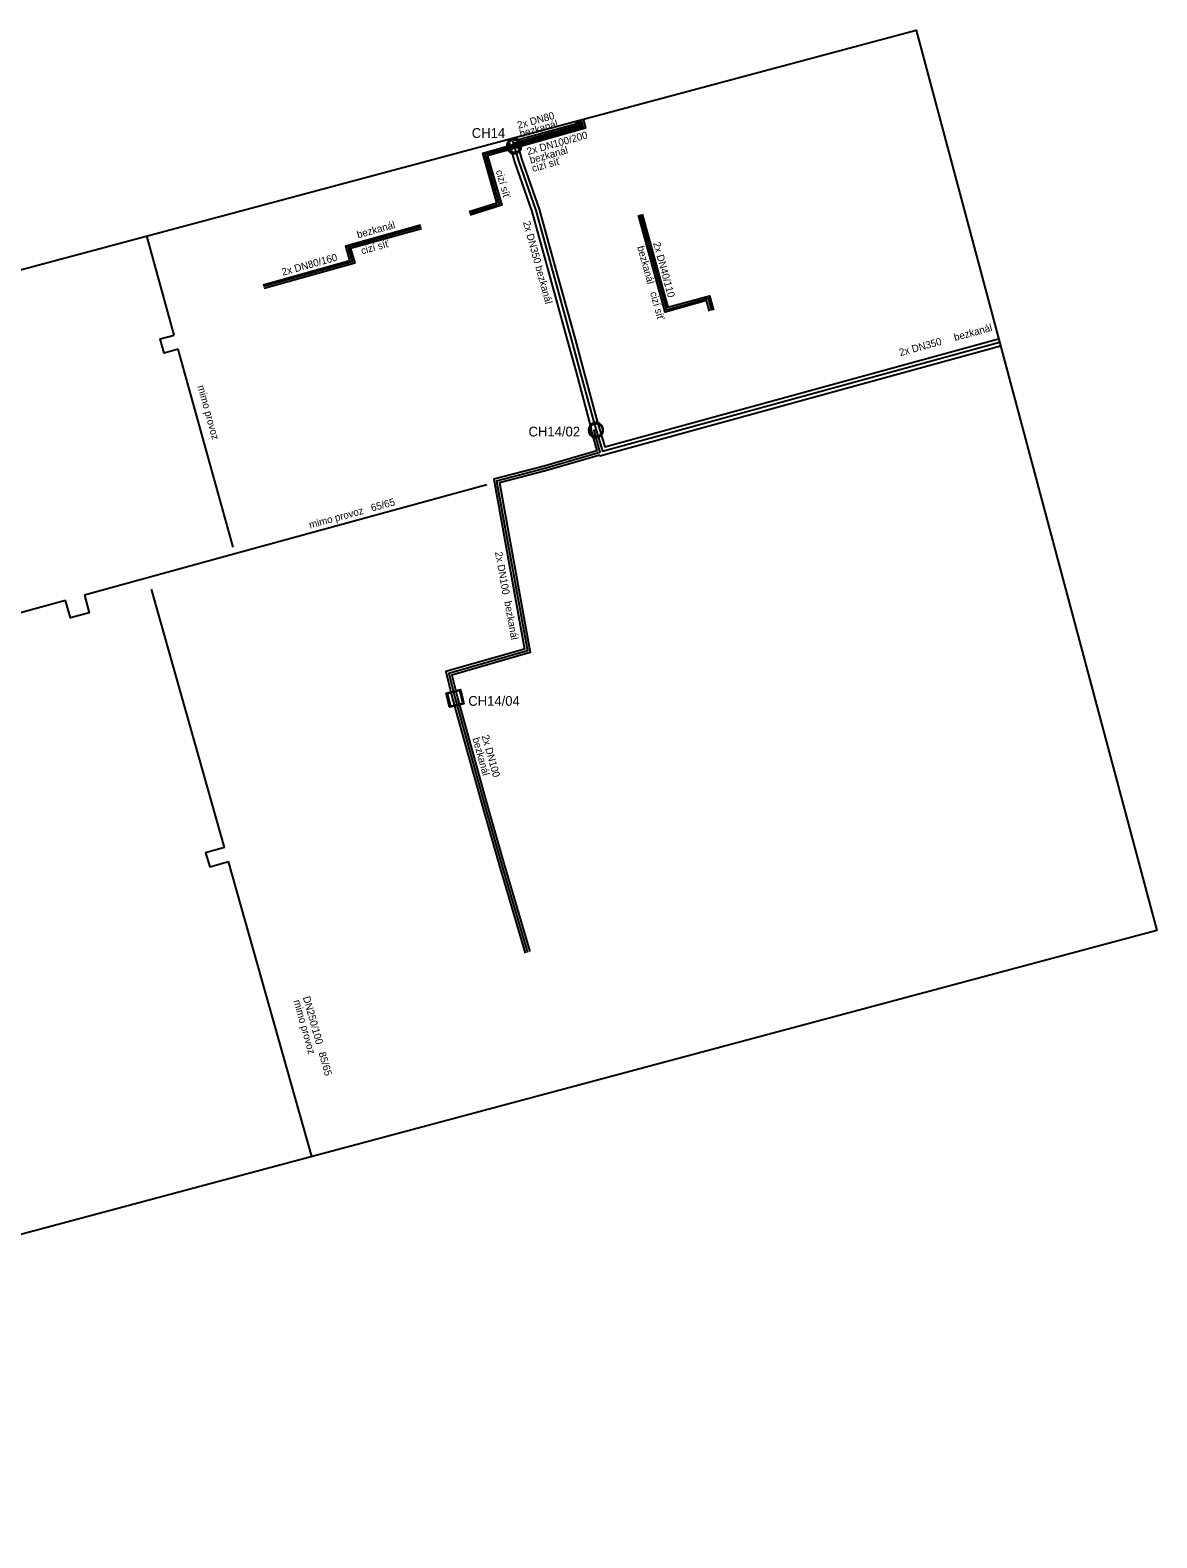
# Model space of a CAD drawing. Extents: x -599341 to -598827, y -1159084 to -1158776.
# Drawn here: x -599057.8 to -598827, y -1159084.3 to -1158775.6 of the extents above; entities that cross this region are included whole.
import ezdxf

# ---------------------------------------------------------------- set-up
doc = ezdxf.new("R2010")
doc.units = 0
for name, color, linetype in [('Horkovod - trasa - okraj', 7, 'Continuous'), ('Horkovod - trasa popis', 7, 'Continuous'), ('Horkovod - trasa popis 2', 7, 'Continuous'), ('Horkovod - trasa popis 3', 7, 'Continuous'), ('Level 46', 7, 'Continuous'), ('Osa trasy horkovodu', 7, 'Continuous'), ('Osa trasy parovodu', 7, 'Continuous'), ('označení', 7, 'Continuous'), ('Parovod - trasa popis', 7, 'Continuous'), ('Parovod - trasa popis 2', 7, 'Continuous'), ('Uzel trasy horkovodu', 7, 'Continuous'), ('Šachta trasy horkovodu', 7, 'Continuous')]:
    doc.layers.add(name, color=color, linetype=linetype)

msp = doc.modelspace()

# ---------------------------------------------------------------- linework, layer by layer
at = {"layer": 'Horkovod - trasa - okraj'}
msp.add_line((-598958.36, -1158797.54), (-598958.2, -1158798.12), dxfattribs=at)
for points in [[(-598967.87, -1158812.7), (-598962.15, -1158810.93), (-598965.07, -1158800.75), (-598945, -1158795.08), (-598945.28, -1158794.04)], [(-598944.51, -1158793.84), (-598944.03, -1158795.64), (-598964.08, -1158801.3), (-598961.17, -1158811.46), (-598967.63, -1158813.46)], [(-598945.18, -1158794.02), (-598944.86, -1158795.24), (-598958.71, -1158799.09)], [(-598958.2, -1158798.12), (-598945.83, -1158794.68), (-598945.95, -1158794.22)], [(-598959.36, -1158799.55), (-598959.54, -1158798.91), (-598959.81, -1158797.93)], [(-598957.81, -1158799.53), (-598957.06, -1158802.12), (-598953.49, -1158812.27), (-598950.63, -1158822.67), (-598946.16, -1158838.89), (-598944.44, -1158845.25), (-598941.49, -1158856.17)], [(-598942.76, -1158857.21), (-598945.89, -1158845.64), (-598947.61, -1158839.29), (-598952.08, -1158823.07), (-598954.92, -1158812.72), (-598958.49, -1158802.57), (-598959.25, -1158799.93)], [(-598918.61, -1158833.13), (-598919.21, -1158830.97), (-598927.71, -1158833.32), (-598933.19, -1158813.48)], [(-598932.42, -1158813.26), (-598927.16, -1158832.34), (-598918.65, -1158829.99), (-598917.84, -1158832.92)], [(-599010.05, -1158827.72), (-598992.28, -1158822.75), (-598993.12, -1158819.76), (-598977.8, -1158815.48)], [(-598977.59, -1158816.25), (-598992.13, -1158820.32), (-598991.29, -1158823.3), (-599009.84, -1158828.49)], [(-598941.49, -1158856.15), (-598940.06, -1158860.91), (-598859.42, -1158838.77)], [(-598941.11, -1158862.63), (-598941.08, -1158862.75), (-598859.03, -1158840.22)], [(-598942.76, -1158857.21), (-598942.93, -1158857.27), (-598941.67, -1158861.75), (-598952.49, -1158864.85), (-598962.8, -1158867.55), (-598956.48, -1158902.33), (-598972.63, -1158906.94), (-598971.23, -1158912.54)], [(-598941.11, -1158862.63), (-598952.23, -1158865.82), (-598961.65, -1158868.29), (-598955.33, -1158903.04), (-598971.42, -1158907.64), (-598970.26, -1158912.29)], [(-598971.23, -1158912.54), (-598964.96, -1158935.04), (-598961.72, -1158946.52), (-598956.35, -1158964.56)], [(-598970.26, -1158912.29), (-598964, -1158934.78), (-598960.76, -1158946.24), (-598955.4, -1158964.27)]]:
    msp.add_lwpolyline(points, dxfattribs=at)
at = {"layer": 'Level 46'}
msp.add_lwpolyline([(-599341.24, -1158899.96), (-598876.32, -1158775.6), (-598827.01, -1158959.94), (-599291.93, -1159084.3)], close=True, dxfattribs=at)
msp.add_lwpolyline([(-599341.24, -1158899.96), (-598876.32, -1158775.6), (-598827.01, -1158959.94), (-599291.93, -1159084.3)], close=True, dxfattribs=at)
at = {"layer": 'Osa trasy horkovodu'}
for points in [[(-598967.75, -1158813.08), (-598961.66, -1158811.2), (-598964.57, -1158801.02), (-598944.52, -1158795.36), (-598944.89, -1158793.94)], [(-598958.82, -1158798.71), (-598945.35, -1158794.96), (-598945.57, -1158794.12)], [(-598959.08, -1158797.73), (-598958.82, -1158798.71), (-598958.64, -1158799.35)], [(-598958.64, -1158799.35), (-598957.77, -1158802.34), (-598954.2, -1158812.49), (-598951.35, -1158822.87), (-598946.88, -1158839.09), (-598945.16, -1158845.45), (-598942.21, -1158856.36)], [(-598932.81, -1158813.37), (-598927.44, -1158832.83), (-598918.93, -1158830.48), (-598918.23, -1158833.03)], [(-598977.7, -1158815.86), (-598992.62, -1158820.04), (-598991.79, -1158823.02), (-599009.95, -1158828.1)], [(-598942.21, -1158856.36), (-598940.57, -1158861.83), (-598859.23, -1158839.5)], [(-598941.89, -1158857.48), (-598942.31, -1158857.6), (-598941.06, -1158862.09), (-598952.36, -1158865.33), (-598962.22, -1158867.92), (-598955.91, -1158902.69), (-598972.03, -1158907.29), (-598970.74, -1158912.42)], [(-598970.74, -1158912.42), (-598964.48, -1158934.91), (-598961.24, -1158946.38), (-598955.88, -1158964.42)]]:
    msp.add_lwpolyline(points, dxfattribs=at)
at = {"layer": 'Osa trasy parovodu'}
for p, q in [((-599028.25, -1158838.02), (-599033.88, -1158817.74)), ((-599016.19, -1158881.44), (-599027.45, -1158840.91)), ((-598964.21, -1158868.66), (-599015.81, -1158882.84)), ((-599015.81, -1158882.84), (-599046.63, -1158891.31)), ((-599017.96, -1158942.93), (-599032.91, -1158890.08)), ((-599050.49, -1158892.36), (-599074.08, -1158898.85)), ((-599000.05, -1159006.22), (-599017.14, -1158945.81))]:
    msp.add_line(p, q, dxfattribs=at)
for points in [[(-599027.45, -1158840.91), (-599030.33, -1158841.71), (-599031.14, -1158838.82), (-599028.25, -1158838.02)], [(-599046.63, -1158891.31), (-599045.66, -1158894.87), (-599049.51, -1158895.93), (-599050.49, -1158892.36)], [(-599017.96, -1158942.93), (-599021.81, -1158944.02), (-599020.99, -1158946.9), (-599017.14, -1158945.81)]]:
    msp.add_lwpolyline(points, dxfattribs=at)
at = {"layer": 'Uzel trasy horkovodu'}
for points in [[(-598957.19, -1158798.93), (-598957.09, -1158799.29), (-598957.17, -1158799.69), (-598957.26, -1158800.09), (-598957.55, -1158800.38), (-598957.84, -1158800.68), (-598958.22, -1158800.79), (-598958.59, -1158800.9), (-598958.99, -1158800.81), (-598959.39, -1158800.72), (-598959.68, -1158800.43), (-598959.97, -1158800.14), (-598960.08, -1158799.76), (-598960.19, -1158799.39), (-598960.1, -1158798.99), (-598960.01, -1158798.59), (-598959.72, -1158798.3), (-598959.43, -1158798.01), (-598959.06, -1158797.9), (-598958.68, -1158797.79), (-598958.28, -1158797.89), (-598957.87, -1158797.98), (-598957.59, -1158798.27), (-598957.3, -1158798.56), (-598957.19, -1158798.93)], [(-598957.37, -1158798.98), (-598957.47, -1158798.66), (-598957.72, -1158798.4), (-598957.97, -1158798.15), (-598958.32, -1158798.07), (-598958.67, -1158797.99), (-598959, -1158798.08), (-598959.33, -1158798.18), (-598959.58, -1158798.43), (-598959.84, -1158798.69), (-598959.92, -1158799.03), (-598960, -1158799.38), (-598959.9, -1158799.71), (-598959.8, -1158800.04), (-598959.55, -1158800.29), (-598959.3, -1158800.55), (-598958.95, -1158800.63), (-598958.6, -1158800.7), (-598958.27, -1158800.61), (-598957.94, -1158800.51), (-598957.69, -1158800.25), (-598957.43, -1158799.99), (-598957.36, -1158799.65), (-598957.28, -1158799.3), (-598957.37, -1158798.98)], [(-598940.44, -1158857.04), (-598940.34, -1158857.4), (-598940.42, -1158857.8), (-598940.5, -1158858.2), (-598940.79, -1158858.5), (-598941.08, -1158858.8), (-598941.45, -1158858.91), (-598941.83, -1158859.03), (-598942.23, -1158858.94), (-598942.62, -1158858.85), (-598942.92, -1158858.57), (-598943.21, -1158858.28), (-598943.32, -1158857.9), (-598943.43, -1158857.53), (-598943.35, -1158857.13), (-598943.26, -1158856.73), (-598942.98, -1158856.44), (-598942.69, -1158856.15), (-598942.32, -1158856.04), (-598941.94, -1158855.92), (-598941.54, -1158856.01), (-598941.13, -1158856.1), (-598940.84, -1158856.39), (-598940.55, -1158856.68), (-598940.44, -1158857.04)], [(-598940.62, -1158857.09), (-598940.72, -1158856.78), (-598940.97, -1158856.52), (-598941.23, -1158856.27), (-598941.58, -1158856.19), (-598941.93, -1158856.12), (-598942.26, -1158856.22), (-598942.59, -1158856.31), (-598942.84, -1158856.57), (-598943.09, -1158856.82), (-598943.16, -1158857.17), (-598943.24, -1158857.52), (-598943.14, -1158857.85), (-598943.04, -1158858.18), (-598942.79, -1158858.43), (-598942.53, -1158858.68), (-598942.18, -1158858.76), (-598941.83, -1158858.83), (-598941.51, -1158858.73), (-598941.18, -1158858.63), (-598940.92, -1158858.37), (-598940.67, -1158858.11), (-598940.6, -1158857.76), (-598940.53, -1158857.41), (-598940.62, -1158857.09)]]:
    msp.add_open_spline(points, degree=3, dxfattribs=at)
at = {"layer": 'Šachta trasy horkovodu'}
for points in [[(-598972.56, -1158911.32), (-598969.65, -1158910.59), (-598968.92, -1158913.51), (-598971.84, -1158914.24), (-598972.56, -1158911.32)], [(-598971.7, -1158914.01), (-598969.15, -1158913.37), (-598969.78, -1158910.82), (-598972.34, -1158911.46), (-598971.7, -1158914.01)]]:
    msp.add_lwpolyline(points, dxfattribs=at)

# ---------------------------------------------------------------- texts
at = {"layer": 'Horkovod - trasa popis'}
for s, rotation, p in [('2x DN80', 15.5511, (-598957.76, -1158795.81)), ('2x DN100/200', 15.7622, (-598955.8, -1158801.19)), ('2x DN350 bezkanál', 285.3606, (-598956.84, -1158814.91)), ('2x DN40/110', 285.4273, (-598930.2, -1158819.19)), ('2x DN80/160', 15.628, (-599006, -1158825.89)), ('2x DN100', 280.3037, (-598962.57, -1158882.51)), ('2x DN100', 285.5575, (-598965.3, -1158920.11))]:
    msp.add_text(s, height=1.5, rotation=rotation, dxfattribs=at).set_placement(p)
at = {"layer": 'Horkovod - trasa popis 2'}
for s, rotation, p in [('bezkanál', 15.5511, (-598957.29, -1158797.56)), ('bezkanál', 15.7622, (-598955.22, -1158802.96)), ('bezkanál', 15.6281, (-598990.61, -1158818.24)), ('bezkanál', 285.4273, (-598933.45, -1158819.98)), ('2x DN350', 15.3516, (-598879.56, -1158842.35)), ('bezkanál', 280.3037, (-598960.66, -1158892.62)), ('bezkanál', 285.5575, (-598967.18, -1158920.63))]:
    msp.add_text(s, height=1.5, rotation=rotation, dxfattribs=at).set_placement(p)
at = {"layer": 'Horkovod - trasa popis 3'}
for s, rotation, p in [('cizí síť', 15.7622, (-598954.77, -1158804.65)), ('cizí síť', 285.9805, (-598962.42, -1158804.44)), ('cizí síť', 15.6281, (-598989.79, -1158821.53)), ('cizí síť', 285.4273, (-598930.82, -1158829.36)), ('bezkanál', 15.3516, (-598868.34, -1158839.26))]:
    msp.add_text(s, height=1.5, rotation=rotation, dxfattribs=at).set_placement(p)
at = {"layer": 'označení'}
for s, p in [('CH14', (-598967.31, -1158797.66)), ('CH14/02', (-598955.69, -1158858.79)), ('CH14/04', (-598968.03, -1158913.94))]:
    msp.add_text(s, height=2, dxfattribs=at).set_placement(p)
at = {"layer": 'Parovod - trasa popis'}
for s, rotation, p in [('mimo provoz', 285.5276, (-599023.51, -1158848.52)), ('mimo provoz   65/65', 15.3553, (-599000.42, -1158877.65)), ('DN250/100   85/65', 285.7913, (-599001.92, -1158973.64))]:
    msp.add_text(s, height=1.5, rotation=rotation, dxfattribs=at).set_placement(p)
at = {"layer": 'Parovod - trasa popis 2'}
msp.add_text('mimo provoz', height=1.5, rotation=285.7989, dxfattribs=at).set_placement((-599003.84, -1158974.36))

doc.saveas('drawing.dxf')
